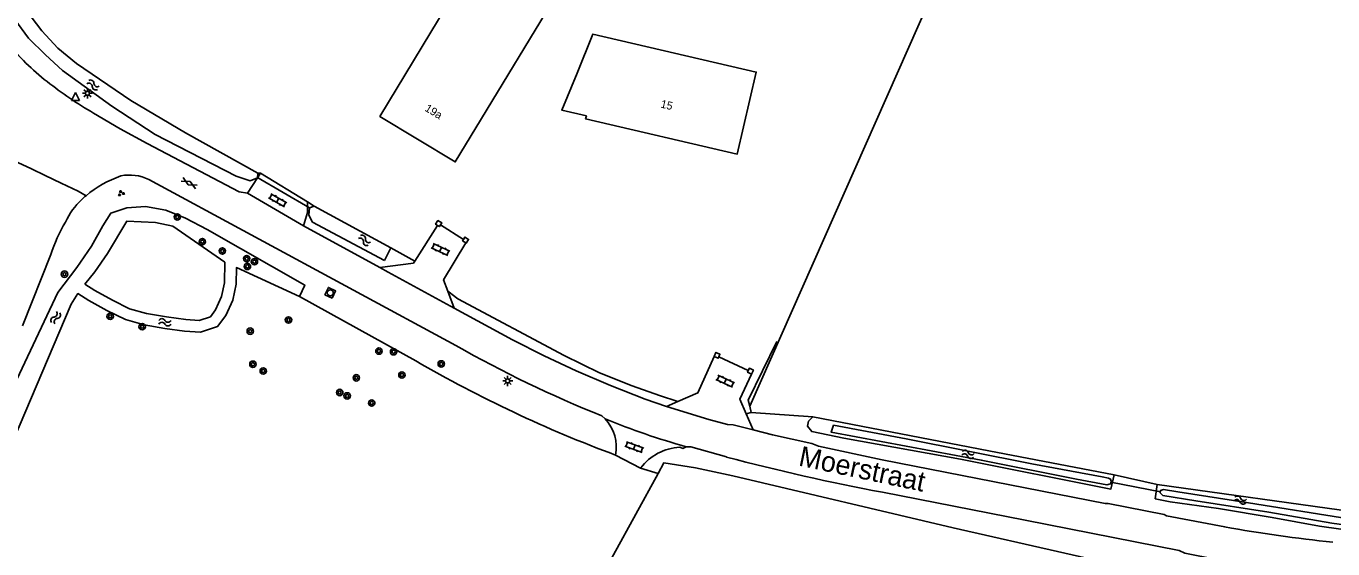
# Model space of a CAD drawing. Extents: x 133000 to 136000, y 400500 to 403500.
# Drawn here: x 134543.9 to 134707.2, y 400609.1 to 400674.4 of the extents above; entities that cross this region are included whole.
import ezdxf

# ---------------------------------------------------------------- set-up
doc = ezdxf.new("R2010")
doc.units = 0
for name, color, linetype in [('gg-afsc-draadraster', 7, 'Continuous'), ('gg-afsc-erfafscheiding', 7, 'Continuous'), ('gg-afsc-hekwerk', 7, 'Continuous'), ('gg-afsc-lijn draadraster', 7, 'Continuous'), ('gg-afsc-muur', 7, 'Continuous'), ('gg-anno-huisnummerreeks BGT', 7, 'Continuous'), ('gg-anno-openbare ruimte label', 7, 'Continuous'), ('gg-bbg-hoofdgebouw', 7, 'Continuous'), ('gg-knt-bronhoudergrens', 7, 'Continuous'), ('gg-knt-verharding', 7, 'Continuous'), ('gg-kntw-bovenkant insteek waterloop', 7, 'Continuous'), ('gg-kntw-waterlijn', 7, 'Continuous'), ('gg-kwrk-duiker nz buis', 7, 'Continuous'), ('gt-grn-groengrens', 7, 'Continuous'), ('gt-grn-weggrens', 7, 'Continuous'), ('gt-symb-boom', 7, 'Continuous'), ('gt-symb-gesloten verharding', 7, 'Continuous'), ('gt-symb-groenvak', 7, 'Continuous'), ('gt-symb-klinker verharding', 7, 'Continuous'), ('gt-symb-lichtmast', 7, 'Continuous'), ('gt-symb-rioolschacht', 7, 'Continuous'), ('gt-symb-waterafsluiter', 7, 'Continuous'), ('gt-symb-watersymbool', 7, 'Continuous')]:
    doc.layers.add(name, color=color, linetype=linetype)

# ---------------------------------------------------------------- blocks, each defined once
blk = doc.blocks.new('gt0-WA')
at = {"layer": 'gt-symb-watersymbool'}
for centre, start, end in [((-0.32, 0.02), 28.0725, 151.9275), ((0.43, 0.42), 208.0725, 331.9275), ((-0.32, -0.43), 28.0725, 151.9275), ((0.43, -0.03), 208.0725, 331.9275)]:
    blk.add_arc(centre, 0.425, start, end, dxfattribs=at)
blk = doc.blocks.new('gt0-KL1')
at = {"layer": 'gt-symb-klinker verharding'}
for p, q in [((-1.15, 0.3), (1.15, 0.3)), ((-1, -0.3), (-1, 0.3)), ((-0.5, 0.3), (-0.5, 0.45)), ((0, -0.3), (0, 0.3)), ((0.5, 0.3), (0.5, 0.45)), ((1, -0.3), (1, 0.3)), ((-1.15, -0.3), (1.15, -0.3)), ((-0.5, -0.45), (-0.5, -0.3)), ((0.5, -0.45), (0.5, -0.3))]:
    blk.add_line(p, q, dxfattribs=at)
blk = doc.blocks.new('gt0-BOOM')
at = {"layer": 'gt-symb-boom'}
for radius in [0.4, 0.2]:
    blk.add_circle((0, 0), radius, dxfattribs=at)
blk = doc.blocks.new('gt0-RS')
at = {"layer": 'gt-symb-rioolschacht'}
blk.add_lwpolyline([(-0.5, -0.5), (0.5, -0.5), (0.5, 0.5), (-0.5, 0.5)], close=True, dxfattribs=at)
blk.add_circle((0, 0), 0.375, dxfattribs=at)
blk = doc.blocks.new('gt0-LMAST')
at = {"layer": 'gt-symb-lichtmast'}
for p, q in [((-0.18, 0.17), (-0.45, 0.44)), ((-0.01, 0.25), (-0.01, 0.62)), ((0.17, 0.17), (0.44, 0.44)), ((-0.26, 0), (-0.63, 0)), ((-0.18, -0.18), (-0.45, -0.45)), ((-0.01, -0.25), (-0.01, -0.63)), ((0.44, -0.45), (0.17, -0.18)), ((0.24, 0), (0.62, 0))]:
    blk.add_line(p, q, dxfattribs=at)
blk.add_circle((-0.01, 0), 0.25, dxfattribs=at)
blk = doc.blocks.new('gt0-WAFSL')
at = {"layer": 'gt-symb-waterafsluiter'}
for p, q in [((-0.5, -0.33), (0, 0.67)), ((0, 0.67), (0.5, -0.33)), ((0.5, -0.33), (-0.5, -0.33))]:
    blk.add_line(p, q, dxfattribs=at)
blk = doc.blocks.new('gt0-GRVAK')
at = {"layer": 'gt-symb-groenvak'}
for p, q in [((-0.11, 0.19), (-0.23, 0.24)), ((-0.18, 0.15), (0.09, 0.15)), ((-0.09, 0.21), (-0.16, 0.32)), ((-0.05, 0.21), (-0.05, 0.39)), ((0, 0.21), (0.06, 0.32)), ((0.01, 0.19), (0.13, 0.24)), ((0.26, -0.05), (0.2, 0.06)), ((0.3, -0.05), (0.3, 0.13)), ((0.35, -0.05), (0.41, 0.06)), ((-0.25, -0.23), (-0.36, -0.18)), ((-0.32, -0.26), (-0.05, -0.26)), ((-0.23, -0.21), (-0.29, -0.1)), ((-0.18, -0.2), (-0.18, -0.02)), ((-0.14, -0.21), (-0.07, -0.1)), ((-0.12, -0.23), (0, -0.18)), ((0.24, -0.07), (0.12, -0.02)), ((0.17, -0.11), (0.44, -0.11)), ((0.37, -0.07), (0.49, -0.02))]:
    blk.add_line(p, q, dxfattribs=at)
blk = doc.blocks.new('gt0-GESVH1')
at = {"layer": 'gt-symb-gesloten verharding'}
for p, q in [((-0.99, -0.26), (0.01, 0.24)), ((0.01, -0.26), (-0.99, 0.24)), ((0.01, 0.24), (1.01, -0.26)), ((1.01, 0.24), (0.01, -0.26))]:
    blk.add_line(p, q, dxfattribs=at)

msp = doc.modelspace()

# ---------------------------------------------------------------- linework, layer by layer
at = {"layer": 'gg-afsc-draadraster'}
for points in [[(134622.84, 400618.55), (134623.56, 400619.85), (134627.51, 400619.24), (134632.17, 400618.23), (134659.73, 400611.75), (134687.64, 400605.4)], [(134622.84, 400618.55), (134614.48, 400603.28), (134604.84, 400585.96), (134602.55, 400587.23), (134599.66, 400584.91), (134597.11, 400582.18), (134601.56, 400578.03), (134603.7, 400575.43)]]:
    msp.add_lwpolyline(points, dxfattribs=at)
at = {"layer": 'gg-afsc-erfafscheiding'}
for p, q in [((134634.49, 400626.15), (134633.85, 400625.99)), ((134634.29, 400626.97), (134634.49, 400626.15))]:
    msp.add_line(p, q, dxfattribs=at)
for points in [[(134625.32, 400627.54), (134623.02, 400628.29), (134619.59, 400629.48), (134615.5, 400631.1), (134611.1, 400633.26), (134597.82, 400640.35), (134596.57, 400641.3)], [(134637.68, 400635.04), (134634.11, 400627.69), (134634.29, 400626.97)]]:
    msp.add_lwpolyline(points, dxfattribs=at)
at = {"layer": 'gg-afsc-hekwerk'}
for p, q in [((134595.63, 400649.59), (134598.52, 400647.79)), ((134630.44, 400633.13), (134634.12, 400631.4))]:
    msp.add_line(p, q, dxfattribs=at)
at = {"layer": 'gg-afsc-lijn draadraster'}
for points in [[(134622.84, 400618.55), (134623.56, 400619.85), (134627.51, 400619.24), (134632.17, 400618.23), (134659.73, 400611.75), (134687.64, 400605.4)], [(134622.84, 400618.55), (134614.48, 400603.28), (134604.84, 400585.96), (134602.55, 400587.23), (134599.66, 400584.91), (134597.11, 400582.18), (134601.56, 400578.03), (134603.7, 400575.43)]]:
    msp.add_lwpolyline(points, dxfattribs=at)
at = {"layer": 'gg-afsc-muur'}
for points in [[(134595.26, 400649.54), (134595.04, 400649.67), (134595.32, 400650.14), (134595.8, 400649.86), (134595.63, 400649.59)], [(134595.63, 400649.59), (134595.51, 400649.39), (134595.26, 400649.54)], [(134598.82, 400647.35), (134598.4, 400647.61), (134598.52, 400647.79)], [(134598.52, 400647.79), (134598.69, 400648.07), (134599.15, 400647.78), (134598.87, 400647.32), (134598.82, 400647.35)], [(134629.85, 400633.15), (134630.06, 400633.66), (134630.57, 400633.44), (134630.44, 400633.13)], [(134629.85, 400633.15), (134630.36, 400632.93), (134630.44, 400633.13)], [(134634.53, 400630.96), (134634.03, 400631.19), (134634.12, 400631.4)], [(134634.12, 400631.4), (134634.26, 400631.69), (134634.76, 400631.46), (134634.53, 400630.96)]]:
    msp.add_lwpolyline(points, dxfattribs=at)
at = {"layer": 'gg-bbg-hoofdgebouw'}
for points in [[(134593.3, 400694.29), (134590.72, 400690.01), (134594.55, 400687.7), (134593.52, 400685.99), (134598.87, 400682.75), (134599.93, 400684.51), (134600.7, 400684.04), (134588.08, 400663.16), (134597.48, 400657.46), (134600.07, 400661.74), (134610.2, 400678.42), (134608.49, 400679.46), (134613.75, 400688.14), (134596.08, 400698.86), (134593.3, 400694.29)], [(134612.71, 400668.57), (134610.81, 400663.95), (134613.88, 400663.23), (134613.78, 400662.84), (134632.73, 400658.44), (134635.11, 400668.68), (134614.67, 400673.42), (134612.71, 400668.57)]]:
    msp.add_lwpolyline(points, dxfattribs=at)
at = {"layer": 'gg-knt-bronhoudergrens'}
msp.add_lwpolyline([(134579.72, 400726.38), (134622.59, 400697.4), (134661.61, 400763.15), (134689.26, 400750.59), (134681.06, 400731.93), (134672.86, 400713.28), (134659.36, 400683.51), (134634.29, 400626.97)], dxfattribs=at)
at = {"layer": 'gg-knt-verharding'}
for p, q in [((134571.54, 400653.58), (134572.76, 400655.48)), ((134572.76, 400655.48), (134573.14, 400656.07)), ((134573.14, 400656.07), (134579.04, 400652.47)), ((134597.57, 400634.53), (134559.18, 400655.25)), ((134578.54, 400649.47), (134571.54, 400653.58)), ((134578.54, 400649.47), (134588.05, 400644.27)), ((134595.26, 400649.54), (134592.43, 400645.08)), ((134546.93, 400645.89), (134543.39, 400636.99)), ((134588.05, 400644.27), (134589.09, 400643.71)), ((134597.34, 400639.21), (134589.09, 400643.71)), ((134596.57, 400641.3), (134597.34, 400639.21)), ((134623.88, 400626.91), (134625.32, 400627.54)), ((134616.23, 400625.37), (134615.8, 400625.76)), ((134633.85, 400625.99), (134634.73, 400623.98)), ((134620.66, 400619.22), (134617.53, 400620.84))]:
    msp.add_line(p, q, dxfattribs=at)
for points in [[(134571.54, 400653.58), (134570.48, 400653.74), (134558.99, 400659.75), (134555.59, 400661.59), (134552.27, 400663.56)], [(134579.04, 400652.47), (134579.04, 400651.14), (134578.54, 400649.47)], [(134598.82, 400647.35), (134596.04, 400642.74), (134596.57, 400641.3)], [(134592.43, 400645.08), (134592.27, 400644.81), (134588.05, 400644.27)], [(134597.34, 400639.21), (134604.65, 400635.23), (134608.59, 400633.24), (134612.59, 400631.37), (134616.88, 400629.54), (134621.23, 400627.84), (134623.88, 400626.91)], [(134629.85, 400633.15), (134627.81, 400628.61), (134625.32, 400627.54)], [(134634.53, 400630.96), (134633.05, 400627.81), (134633.85, 400625.99)], [(134623.88, 400626.91), (134629.17, 400625.29), (134631.5, 400624.66), (134632.22, 400624.6), (134634.73, 400623.98)], [(134634.73, 400623.98), (134637.13, 400623.38), (134642.07, 400622.29), (134642.88, 400621.97), (134650.83, 400620.25), (134678.73, 400614.8), (134679.08, 400614.81), (134686.11, 400613.42), (134686.39, 400613.24), (134693.66, 400611.86)], [(134626.35, 400621.88), (134625.94, 400621.67), (134625.55, 400621.82)], [(134631.41, 400620.6), (134626.92, 400621.89), (134626.35, 400621.88)], [(134709.66, 400605.01), (134697.82, 400607.16), (134697.41, 400607.12), (134696.74, 400607.16), (134692.7, 400607.81), (134688.68, 400608.6), (134687.96, 400608.9), (134668.72, 400612.72), (134650.88, 400616.2)]]:
    msp.add_lwpolyline(points, dxfattribs=at)
for centre, radius, start, end in [((134564.81, 400691.13), 29.91, 218.738, 232.1767), ((134579.06, 400709.24), 52.95, 232.0191, 239.6127), ((134560.32, 400642.48), 14.02, 109.3169, 129.8398), ((134556.78, 400650.46), 5.37, 63.4015, 101.7722), ((134557.52, 400645.76), 9.71, 133.6288, 154.4174), ((134559.78, 400643.07), 13.22, 129.6883, 132.6836), ((134567.83, 400638.89), 22.04, 149.8785, 161.4867), ((134669.43, 400760.53), 145.05, 240.3012, 248.2989), ((134651.31, 400710.69), 92.25, 247.6479, 254.3009), ((134612.39, 400621.82), 5.23, 349.1958, 42.8319), ((134625.9, 400615.27), 6.56, 93.0133, 142.9125), ((134699.27, 400875.94), 264.21, 255.1167, 259.4458), ((134729.12, 400813.98), 205.21, 260.0491, 263.8627)]:
    msp.add_arc(centre, radius, start, end, dxfattribs=at)
at = {"layer": 'gg-kntw-bovenkant insteek waterloop'}
for p, q in [((134572.83, 400656.08), (134572.76, 400655.48)), ((134579.87, 400651.94), (134589.42, 400646.72)), ((134588.66, 400645.15), (134589.42, 400646.72))]:
    msp.add_line(p, q, dxfattribs=at)
for points in [[(134560.18, 400706.18), (134561.4, 400706.43), (134562.13, 400706.1), (134561.66, 400705.62), (134560.56, 400704.36), (134554.96, 400698.43), (134542.6, 400686.26), (134540.86, 400684.23), (134540.67, 400683.33), (134541.25, 400681.41), (134542.39, 400678.75), (134543.94, 400676.29), (134545.8, 400673.86), (134547.81, 400671.67), (134550.14, 400669.77), (134556.92, 400665.14), (134563.77, 400661.11), (134572.83, 400656.08)], [(134572.76, 400655.48), (134571.84, 400655.12), (134570.11, 400655.69), (134560, 400660.91), (134554.58, 400664.43), (134548.4, 400668.89), (134546.28, 400670.83), (134544.16, 400672.92), (134542.45, 400675.24), (134539.66, 400679.41), (134538.84, 400681.25), (134538.2, 400682.93), (134538.15, 400683.98), (134538.53, 400684.92), (134539.07, 400685.51)], [(134578.01, 400640.64), (134578.67, 400642.07), (134566.48, 400649.02), (134563.78, 400650.43), (134561.32, 400651.43), (134558.78, 400651.89), (134556.42, 400651.73), (134554.44, 400651.06), (134553.43, 400649.5), (134552.02, 400646.95), (134550.21, 400644.27), (134547.83, 400641.16), (134540.55, 400625.88), (134534.6, 400610.09), (134536.58, 400609.41)], [(134588.66, 400645.15), (134579.64, 400649.95), (134579.18, 400650.82), (134579.26, 400651.71), (134579.87, 400651.94)], [(134551.21, 400642.18), (134552.44, 400641.41), (134554.63, 400640.2), (134556.78, 400639.13), (134558.91, 400638.54), (134561.4, 400638.1), (134563.81, 400637.76), (134565.47, 400637.66), (134566.89, 400638.13), (134567.54, 400639), (134568.29, 400640.64), (134568.66, 400642.37), (134568.69, 400644.93), (134562.19, 400649.45), (134560.01, 400649.89), (134556.46, 400650.08), (134554.04, 400646.02), (134552.44, 400643.73), (134551.21, 400642.18)], [(134536.58, 400609.41), (134549.47, 400639.69), (134550.32, 400641.02), (134551.7, 400640.15), (134553.95, 400638.91), (134556.26, 400637.76), (134558.59, 400637.12), (134561.17, 400636.66), (134563.66, 400636.31), (134565.66, 400636.18), (134567.79, 400636.9), (134568.8, 400638.26), (134569.68, 400640.18), (134570.11, 400642.21), (134570.14, 400644.26), (134578.01, 400640.64)], [(134679.85, 400618.38), (134679.45, 400616.6), (134660.64, 400620.31), (134646.07, 400622.95), (134642.05, 400623.77), (134641.52, 400624.44), (134641.65, 400625.09), (134642.17, 400625.62)], [(134642.17, 400625.62), (134664.19, 400621.37), (134679.85, 400618.38)], [(134685.22, 400617.17), (134684.98, 400615.38), (134686.86, 400615.01), (134692.9, 400614.15), (134699.59, 400613.03), (134705.52, 400611.95), (134711.12, 400611.16), (134720.27, 400610.65), (134731.88, 400609.94), (134738.58, 400610.48), (134750.35, 400611.36), (134759.37, 400611.84), (134765.71, 400612.49), (134769.45, 400613.14), (134769.28, 400614.85)], [(134727.04, 400612.26), (134715.7, 400613.02), (134709.77, 400613.76), (134685.22, 400617.17)]]:
    msp.add_lwpolyline(points, dxfattribs=at)
at = {"layer": 'gg-kntw-waterlijn'}
for points in [[(134679.49, 400617.58), (134679.38, 400617.23), (134678.95, 400617.13), (134675.15, 400617.83), (134663.24, 400620.22), (134644.46, 400623.71), (134644.77, 400624.57), (134653.87, 400622.86), (134669.56, 400619.75), (134678.33, 400618.13), (134679.13, 400617.96), (134679.41, 400617.83), (134679.49, 400617.58)], [(134686.02, 400616.53), (134685.62, 400616.42), (134685.61, 400616.11), (134685.95, 400615.81), (134690.07, 400615.11), (134699.19, 400613.7), (134707.07, 400612.32), (134713.82, 400611.42), (134723.32, 400610.74), (134728.85, 400610.44), (134735.46, 400610.65), (134746.25, 400611.31), (134749.26, 400611.75), (134749.18, 400612.3), (134736.21, 400611.68), (134726.65, 400611.42), (134716.21, 400612.16), (134709.17, 400612.89), (134696.65, 400614.89), (134687.79, 400616.26), (134686.02, 400616.53)]]:
    msp.add_lwpolyline(points, dxfattribs=at)
at = {"layer": 'gg-kwrk-duiker nz buis'}
for p, q in [((134572.69, 400655.55), (134579.26, 400651.71)), ((134679.43, 400617.47), (134685.62, 400616.26))]:
    msp.add_line(p, q, dxfattribs=at)
at = {"layer": 'gt-grn-groengrens'}
for p, q in [((134572.83, 400656.08), (134573.14, 400656.07)), ((134579.04, 400652.47), (134579.87, 400651.94)), ((134592.43, 400645.08), (134589.42, 400646.72)), ((134578.01, 400640.64), (134592.56, 400632.61)), ((134634.49, 400626.15), (134642.17, 400625.62)), ((134620.66, 400619.22), (134622.84, 400618.55)), ((134679.85, 400618.38), (134685.22, 400617.17))]:
    msp.add_line(p, q, dxfattribs=at)
msp.add_arc((134673.39, 400771.69), 160.86, 239.8391, 249.6808, dxfattribs=at)
at = {"layer": 'gt-grn-weggrens'}
msp.add_lwpolyline([(134551.34, 400653.24), (134550.36, 400653.82), (134548.22, 400654.8), (134546.25, 400655.79), (134544.54, 400656.6), (134541.75, 400657.89), (134540.32, 400658.54)], dxfattribs=at)

# ---------------------------------------------------------------- block references
at = {"layer": 'gt-symb-boom'}
for p in [(134562.75, 400650.59), (134565.88, 400647.5), (134568.38, 400646.34), (134571.42, 400645.38), (134571.51, 400644.41), (134572.39, 400645), (134548.65, 400643.44), (134554.36, 400638.17), (134576.65, 400637.72), (134558.36, 400636.88), (134571.86, 400636.32), (134587.95, 400633.83), (134572.2, 400632.19), (134589.78, 400633.75), (134595.74, 400632.23), (134573.49, 400631.34), (134590.82, 400630.84), (134585.12, 400630.49), (134583.05, 400628.66), (134583.98, 400628.23), (134587.05, 400627.34)]:
    msp.add_blockref('gt0-BOOM', p, dxfattribs=at)
at = {"layer": 'gt-symb-gesloten verharding', "rotation": -28.409358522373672}
msp.add_blockref('gt0-GESVH1', (134564.24, 400654.83), dxfattribs=at)
at = {"layer": 'gt-symb-groenvak'}
msp.add_blockref('gt0-GRVAK', (134555.71, 400653.55), dxfattribs=at)
at = {"layer": 'gt-symb-klinker verharding'}
for p, rotation in [((134575.3, 400652.66), -29.41081962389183), ((134595.65, 400646.52), -24.643095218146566), ((134631.24, 400630.07), -24.643095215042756), ((134619.87, 400621.83), 160.0609520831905)]:
    msp.add_blockref('gt0-KL1', p, dxfattribs=dict(at, rotation=rotation))
at = {"layer": 'gt-symb-lichtmast'}
for p in [(134551.53, 400666.04), (134604.05, 400630.1)]:
    msp.add_blockref('gt0-LMAST', p, dxfattribs=at)
at = {"layer": 'gt-symb-rioolschacht', "rotation": 63.94764904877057}
msp.add_blockref('gt0-RS', (134581.87, 400641.11), dxfattribs=at)
at = {"layer": 'gt-symb-waterafsluiter'}
msp.add_blockref('gt0-WAFSL', (134550.04, 400665.45), dxfattribs=at)
at = {"layer": 'gt-symb-watersymbool'}
for p, rotation in [((134552.18, 400667.11), -28.025316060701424), ((134586.09, 400647.7), -34.61180636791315), ((134547.52, 400637.95), 66.74124066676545), ((134661.52, 400620.94), -9.84862238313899), ((134695.56, 400615.23), -9.725965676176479)]:
    msp.add_blockref('gt0-WA', p, dxfattribs=dict(at, rotation=rotation))
msp.add_blockref('gt0-WA', (134561.14, 400637.44), dxfattribs=at)

# ---------------------------------------------------------------- texts
at = {"layer": 'gg-anno-huisnummerreeks BGT'}
for s, rotation, p in [('19a', 328.7, (134593.59, 400663.91)), ('15', 346.9, (134623.09, 400664.27))]:
    msp.add_text(s, height=1, rotation=rotation, dxfattribs=at).set_placement(p)
at = {"layer": 'gg-anno-openbare ruimte label'}
msp.add_text('Moerstraat', height=2.5, rotation=348.1, dxfattribs=at).set_placement((134640.29, 400619.55))

doc.saveas('drawing.dxf')
